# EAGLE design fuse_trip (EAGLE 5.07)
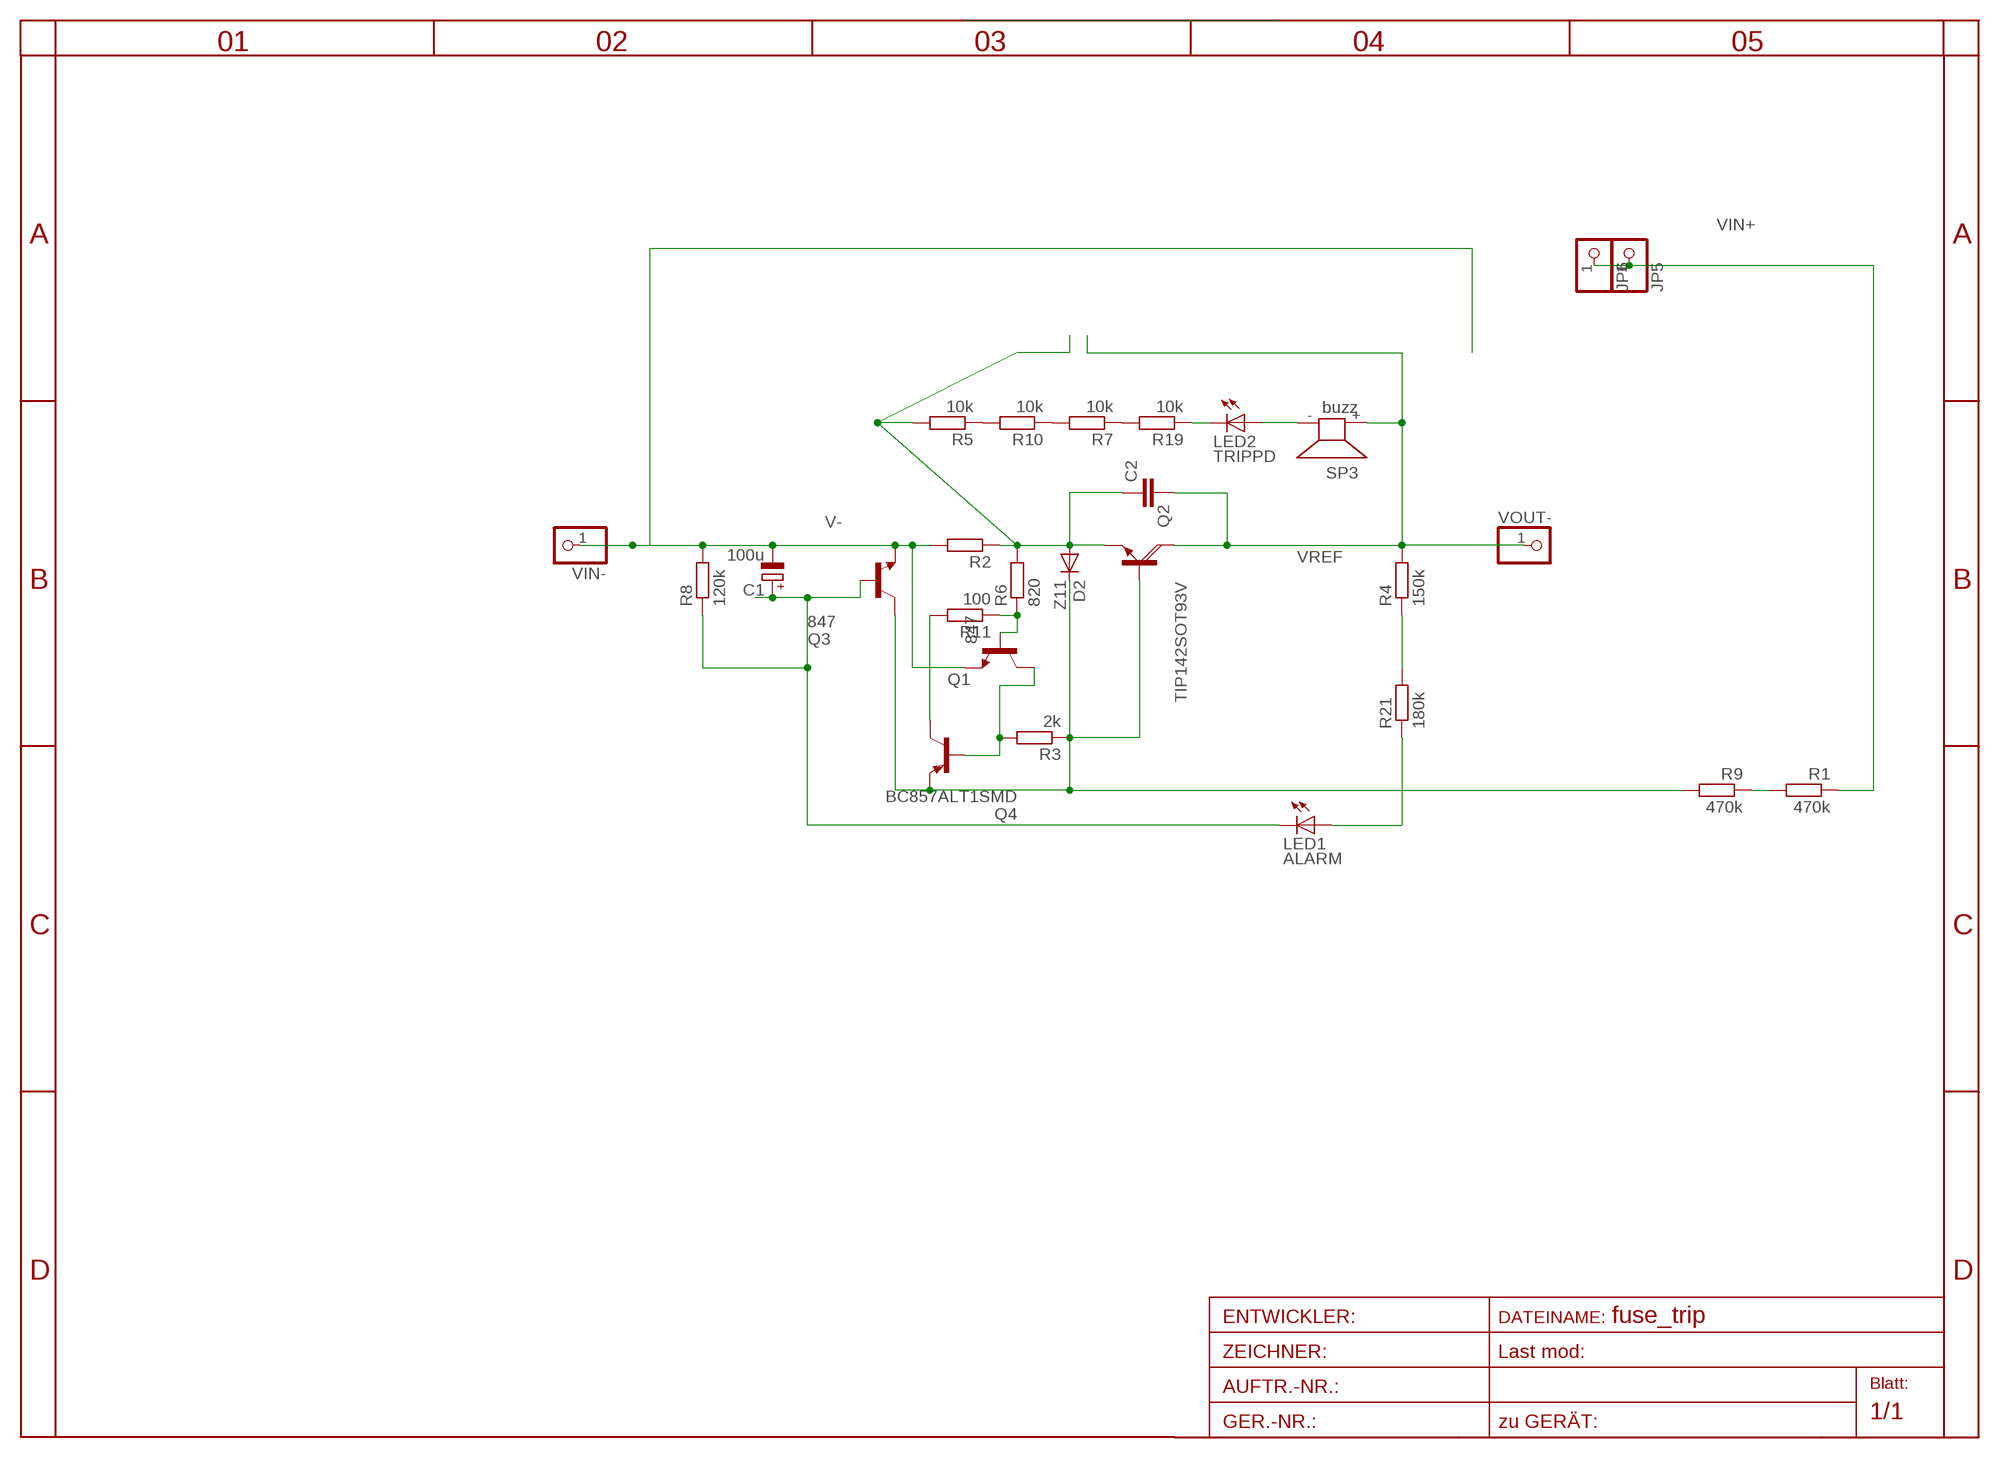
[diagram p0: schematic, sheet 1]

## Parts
C1  100u  CPOL-EUE2.5-5  [E2,5-5]
C2  C-EU225-062X268  [C225-062X268]
D2  Z11  DIODE-MINIMELF  [MINIMELF]
JP5  PINHD-1X12MM3  [1X2MM3]
JP6  PINHD-1X12MM3  [1X2MM3]
LED1  ALARM  LED5MM  [LED5MM]
LED2  TRIPPD  LED5MM  [LED5MM]
Q1  847  BC847ALT1SMD  [SOT23]
Q2  TIP142SOT93V  [SOT93V]
Q3  847  BC847ALT1SMD  [SOT23]
Q4  BC857ALT1SMD  [SOT23-BEC]
R1  470k  R-EU_R1206  [R1206]
R2  R-EU_0411/12  [0411/12]
R3  2k  R-EU_R0805  [R0805]
R4  150k  R-EU_R1206  [R1206]
R5  10k  R-EU_R1206  [R1206]
R6  820  R-EU_R1206  [R1206]
R7  10k  R-EU_R1206  [R1206]
R8  120k  R-EU_R0805  [R0805]
R9  470k  R-EU_R1206  [R1206]
R10  10k  R-EU_R1206  [R1206]
R11  100  R-EU_R0805  [R0805]
R19  10k  R-EU_R1206  [R1206]
R21  180k  R-EU_R1206  [R1206]
SP3  buzz  KSS12017MM  [KSS1202]
VIN-  PINHD-1X12MM3  [1X2MM3]
VOUT-  PINHD-1X12MM3  [1X2MM3]

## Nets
A1: LED2.A SP3.-
E1: C2.1 D2.A Q2.E R2.1 R5.2 R6.2
GATE: D2.C Q2.B Q3.3(C) Q4.E R3.1 R9.2
N$1: R7.2 R10.1
N$2: R5.1 R10.2
N$3: Q4.C R11.2
N$6: Q1.1(B) R6.1 R11.1
N$7: Q1.3(C) Q4.B R3.2
N$9: LED2.K(C) R19.1
N$11: LED1.A R21.1
N$20: R1.2 R9.1
N$21: R7.1 R19.2
N$22: R4.1 R21.2
SIGN: C1.+ LED1.K(C) Q3.1(B) R8.1
V-: C1.- Q1.2(E) Q3.2(E) R2.2 R8.2 VIN-.1
VIN+: JP5.1 JP6.1 R1.1
VREF: C2.2 Q2.C R4.2 SP3.+ VOUT-.1

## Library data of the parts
C1 = rcl:CPOL-EU: POLARIZED CAPACITOR, European symbol
C2 = rcl:C-EU: CAPACITOR, European symbol
D2 = diode:DIODE-: DIODE
JP5 JP6 VIN- VOUT- = pinhead:PINHD-1X1: PIN HEADER
LED1 LED2 = led:LED: LED
Q1 Q3 = transistor-npn:BC847*: NPN Transistor
Q2 = transistor-power:TIP142: NPN DARLINGTON TRANSISTOR
Q4 = transistor-pnp:BC857*: PNP Transistror
R1 R3-R11 R19 R21 = rcl:R-EU_: RESISTOR, European symbol
R2 = rcl-2:R-EU_: RESISTOR, European symbol
SP3 = buzzer:KSS1201: SPEAKER

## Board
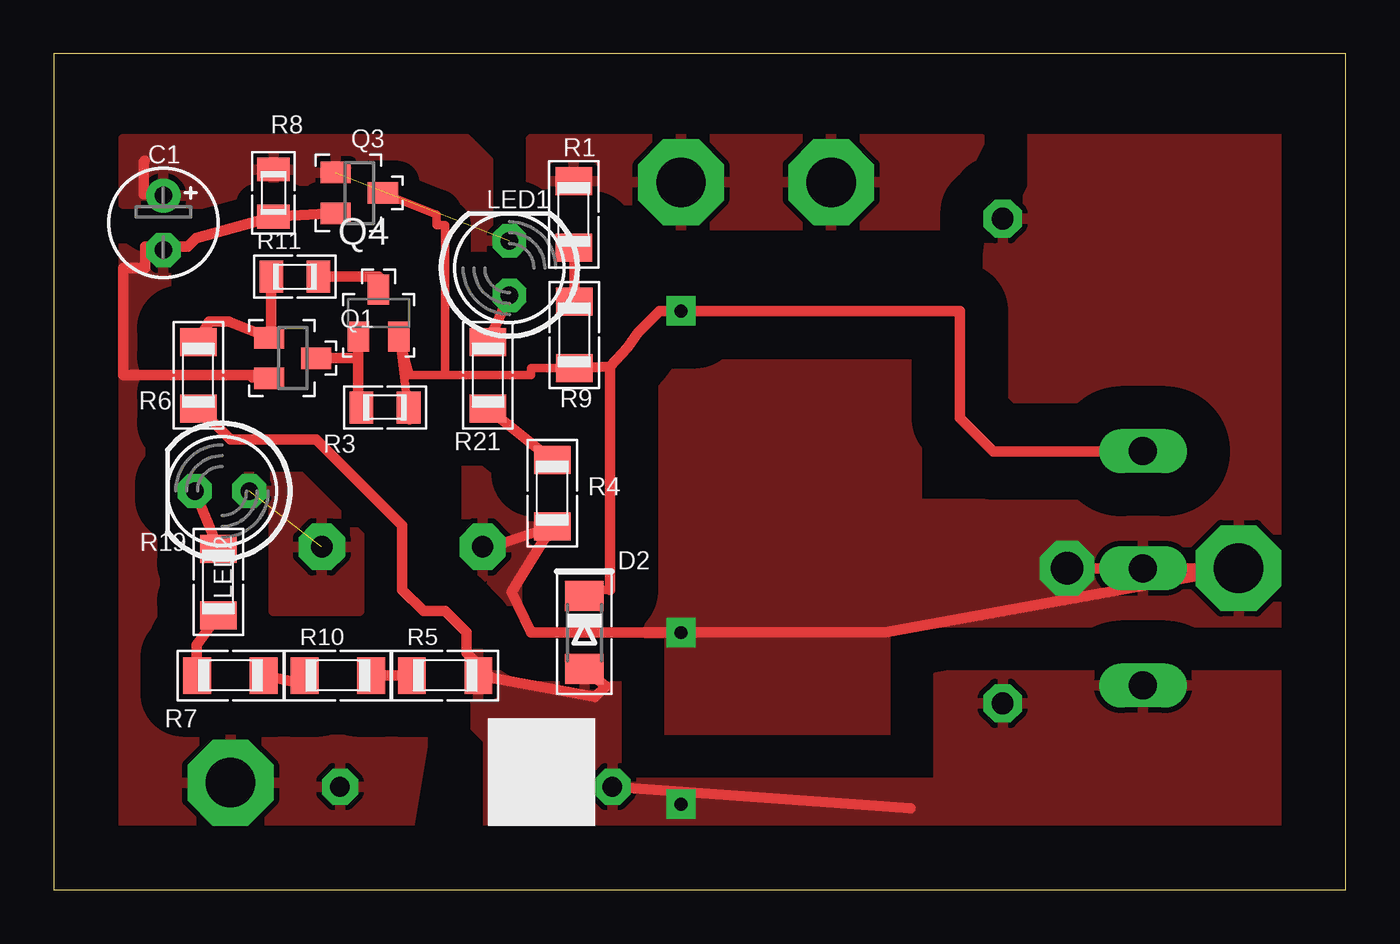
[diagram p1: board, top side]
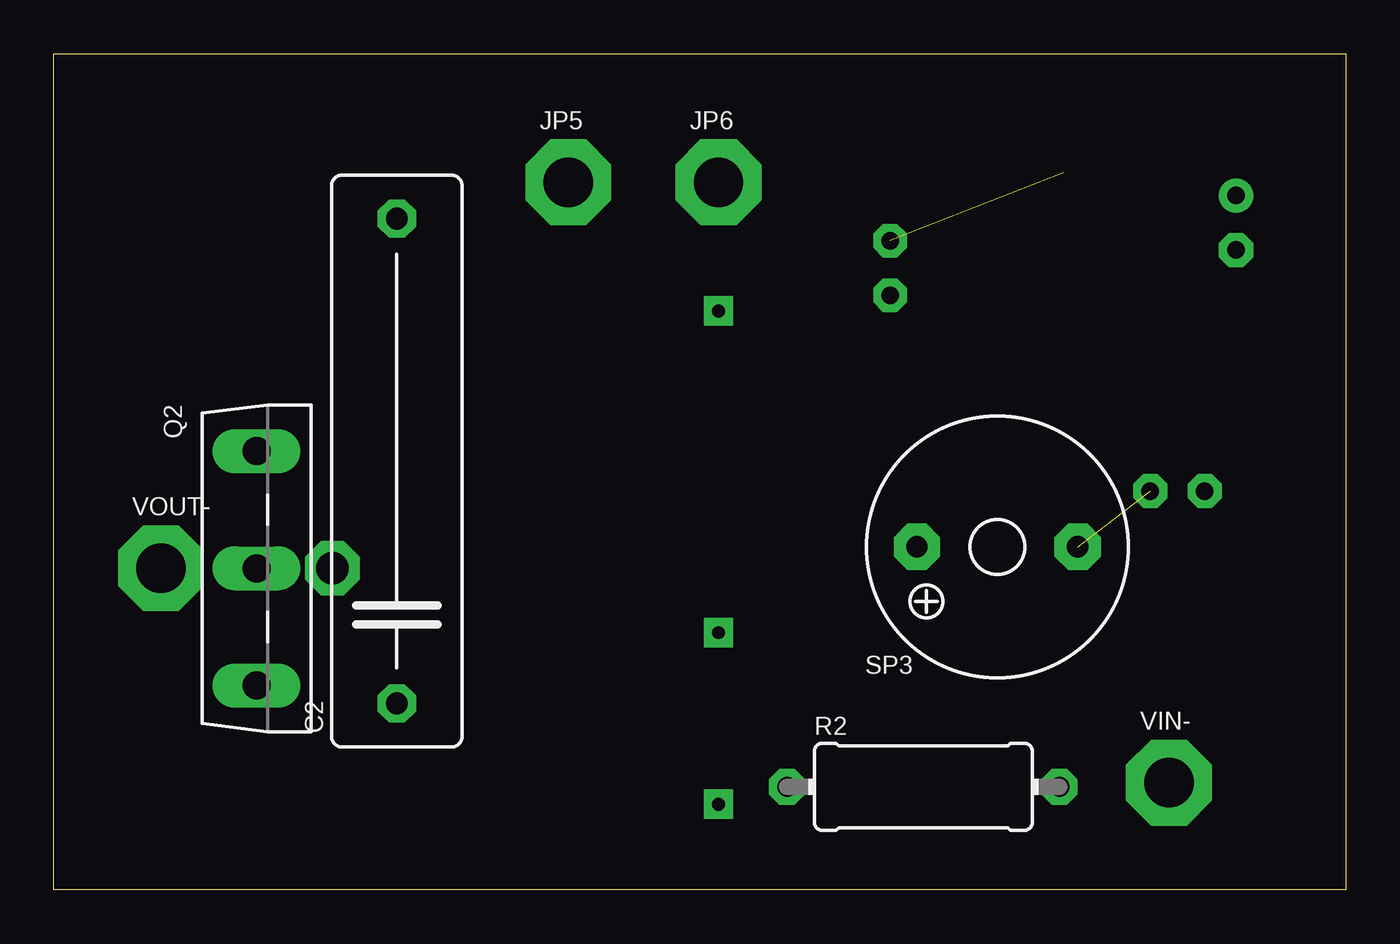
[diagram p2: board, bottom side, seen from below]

Size 60.25 x 39 mm. Coordinates in mm from the lower left corner, seen from the top.
Outline: 60.25,0 60.25,39 0,39 0,0 60.25,0
Copper layers (1*16): Top 0.035mm / dielectric 1.5mm / Bottom 0.035mm
Design rules "default *": minimum track width 10mil, minimum drill 2mil, track to track 8mil, track to pad 8mil, pad to pad 8mil, via to via 8mil, smd to smd 8mil, copper to edge 3mm, drill to drill 8mil, minimum pad ring 15mil, minimum via ring 15mil, stop-mask expansion 4mil, vias tented up to drill 0mil, thermal gap 10mil

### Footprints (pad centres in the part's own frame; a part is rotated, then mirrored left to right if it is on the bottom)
E2,5-5 = drill 0.813 pad 1.6 round: + -1.27,0 | drill 0.813 pad 1.6 octagon: - 1.27,0
C225-062X268 = drill 1.016 octagon: 1 -11.303,0; 2 11.303,0
MINIMELF = smd 1.4 x 1.8: A 1.7,0; C -1.7,0
1X2MM3 = drill 2.3 pad 4 octagon: 1 0,0
LED5MM = drill 0.813 octagon: A -1.27,0; K 1.27,0
SOT23 = smd 1 x 1.4: 1 -0.95,-1.1; 2 0.95,-1.1; 3 0,1.1
SOT93V = drill 1.3 pad 1.676 long: B -5.461,-2.54; C 0,-2.54; E 5.461,-2.54
SOT23-BEC = smd 1 x 1.4: B -0.95,-1.1; C 0,1.1; E 0.95,-1.1
R1206 = smd 1.3 x 1.7: 1 -1.55,0; 2 1.55,0
0411/12 = drill 0.914 octagon: 1 -6.35,0; 2 6.35,0
R0805 = smd 1.1 x 1.5: 1 -1.1,0; 2 1.1,0
KSS1202 = drill 1 pad 2.159 octagon: + 3.75,0; - -3.75,0

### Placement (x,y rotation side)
C1  5.12,31.11 270 top
C2  44.25,20 90 bottom
D2  24.75,12 270 top
JP5  36.25,33 0 bottom
JP6  29.25,33 0 bottom
LED1  21.25,29 90 top
LED2  7.85,18.6 180 top
Q1  11.15,24.8 270 top
Q2  48.25,15 270 bottom
Q3  14.25,32.5 270 top
Q4  15.15,26.9 0 top
R1  24.25,31.5 270 top
R2  19.7,4.81 0 bottom
R3  15.45,22.5 180 top
R4  23.25,18.5 270 top
R5  18.25,10 0 top
R6  6.75,24 270 top
R7  8.25,10 0 top
R8  10.25,32.5 270 top
R9  24.28,25.88 270 top
R10  13.25,10 0 top
R11  11.25,28.6 0 top
R19  7.68,14.36 270 top
R21  20.25,24 270 top
SP3  16.25,16 180 bottom
VIN-  8.25,5 0 bottom
VOUT-  55.25,15 0 bottom

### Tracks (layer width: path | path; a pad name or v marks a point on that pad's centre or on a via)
A1  (1 unrouted)
  pour Top (isolate 1.27, rank 3): 7.25,23 10.25,23 14.25,19 14.25,13 10.25,13 10.25,18 9.25,19 7.25,19
E1  (via drill 0.6)
  Top 0.5: R2.1 39.95,3.81 | D2.A 25.75,9.5 25.25,9 20.41,9.89 | R5.2 20.41,9.89 | R6.2 6.8,22.45 8.25,21 12.25,21 16.25,17 16.25,14 17.25,13 18.25,13 19.25,12 19.25,11.05 20.41,9.89
  other vias: 29.25,4
  pour Top (isolate 2, rank 2): 18.25,11 18.25,8 19.25,8 20.25,7 20.25,2 57.25,2 57.25,10 41.25,10 41.25,5 26.25,5 26.25,11
GATE  (via drill 0.6)
  Top 0.406: 25.95,14 24.75,14 D2.C | Q3.3 17.85,31.5 17.85,31 18.25,31 18.25,24 | 18.25,24 16.6,24 Q4.E 16.6,21.9 R3.1 | R9.2 22.25,24.33 22.25,24 18.25,24
  Top 0.5: Q2.B 50.3,20.45 43.81,20.45 42.25,22 42.25,27 v29.25,27 28.25,27 27.25,26 26.75,25.3 25.95,24.4 | 25.95,24.4 25.95,14 | R9.2 24.32,24.33 25.95,24.4
N$1
  Top 0.5: R7.2 11.22,9.71 R10.1
N$2
  Top 0.5: R10.2 R5.1
N$3
  Top 0.5: R11.2 15.15,28.6 Q4.C
N$6
  Top 0.5: R6.1 7.25,26.5 8.15,26.5 Q1.1 10.15,25.75 R11.1
N$7
  Top 0.5: R3.2 14.2,22.5 14.2,24.8 | Q4.B 14.2,25 14.2,24.8 | Q1.3 14.2,24.8
N$9
  Top 0.5: LED2.K 7.65,16.01 R19.1
N$11
  Top 0.5: R21.1 LED1.A
N$20
  Top 0.5: R9.1 24.28,29.97 R1.2
N$21
  Top 0.5: R19.2 6.68,11.44 R7.1
N$22
  Top 0.5: R21.2 R4.1
SIGN  (1 unrouted)
  Top 0.5: C1.+ 4.19,32.45 4.19,33.94 4.25,34
  pour Top (isolate 1, rank 2): 3.25,32 3.25,35 19.25,35 20.25,34 20.25,30 18.25,30 18.25,32
V-
  Top 0.406: Q1.2 9.25,23.85 9.25,24
  Top 0.5: Q3.2 R8.2 6.65,30.4 6.25,30 4.28,30 | 4.28,30 C1.- | 9.25,24 3.25,24 3.25,29 4.28,29 4.28,30
  pour Top (isolate 2): 2.25,31 5.25,31 5.25,7 17.25,7 16.25,1 1.25,1
VIN+
  pour Top (isolate 2): 22.25,35 43.25,35 41.25,31 22.25,31
VREF  (via drill 0.6, 1.5 pad 2.54)
  Top 0.5: SP3.+ 20.35,15.98 R4.2 21.35,13.9 22.25,12 v29.25,12 38.75,12 VOUT-.1 | VOUT-.1 v47.25,15 Q2.C VOUT-.1
  pour Top (isolate 2, rank 4): 43.25,35 58.25,35 57.25,12 41.25,12 41.25,7 19.25,7 19.25,25 40.25,25 40.25,18 53.25,18 53.25,22 41.25,22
